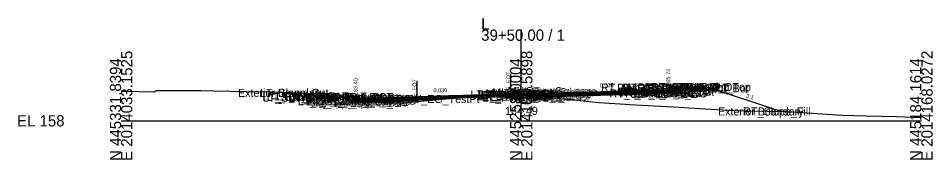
# Model space of a CAD drawing. Extents: x -26 to 4203, y -10 to 9526.
# Drawn here: x 1974.3 to 2202.8, y 9490.3 to 9525.6 of the extents above; entities that cross this region are included whole.
import ezdxf

# ---------------------------------------------------------------- set-up
doc = ezdxf.new("R2010")
doc.units = 0
for name, color, linetype in [('Default', 7, 'Continuous'), ('Exist CMT Pavement', 7, 'Continuous'), ('Exist Cross Section Cell', 7, 'Continuous'), ('Exist XS Center Line Elevation Label', 7, 'Continuous'), ('Exist XS Ground Line', 7, 'Continuous'), ('Prop CMT Conc Surface', 7, 'Continuous'), ('Prop CMT Concrete Structures', 7, 'Continuous'), ('Prop CMT Pvmt Course 1', 7, 'Continuous'), ('Prop CMT Pvmt Course 1 CG', 7, 'Continuous'), ('Prop CMT Pvmt Course 1 Wedge', 7, 'Continuous'), ('Prop CMT Pvmt Course 2', 7, 'Continuous'), ('Prop CMT Pvmt Course 2 Wedge', 7, 'Continuous'), ('Prop CMT Pvmt Course 3', 7, 'Continuous'), ('Prop CMT Pvmt Course 3 Wedge', 7, 'Continuous'), ('Prop CMT Pvmt Surface', 7, 'Continuous'), ('Prop CMT Pvmt Wedge Surface 1', 7, 'Continuous'), ('Prop CMT Pvmt Wedge Surface 2', 7, 'Continuous'), ('Prop CMT Pvmt Wedge Surface 3', 7, 'Continuous'), ('Prop CMT Slope Grass', 7, 'Continuous'), ('Prop CMT Subgrade Earthwork', 7, 'Continuous'), ('Prop XS Hydro Elevations', 7, 'Continuous'), ('Prop XS Label Text', 7, 'Continuous'), ('Prop XS SE Text', 7, 'Continuous'), ('Prop XS Side Slope Text', 7, 'Continuous'), ('Scratch_Level_0', 7, 'Continuous')]:
    doc.layers.add(name, color=color, linetype=linetype)

msp = doc.modelspace()

# ---------------------------------------------------------------- linework, layer by layer
at = {"layer": 'Exist CMT Pavement'}
for p, q in [((2073.93, 9504.85), (2080.3, 9505.44)), ((2080.3, 9505.44), (2082.24, 9505.6)), ((2082.24, 9505.6), (2084.36, 9505.77)), ((2084.36, 9505.77), (2087.3, 9506.01)), ((2087.3, 9506.01), (2088.91, 9506.12)), ((2088.91, 9506.12), (2090.43, 9506.24)), ((2090.43, 9506.24), (2091.02, 9506.29)), ((2091.02, 9506.29), (2092.45, 9506.38)), ((2092.45, 9506.38), (2093.81, 9506.46)), ((2093.81, 9506.46), (2096.86, 9506.66)), ((2096.86, 9506.66), (2097.34, 9506.68))]:
    msp.add_line(p, q, dxfattribs=at)
at = {"layer": 'Exist Cross Section Cell'}
for p, q in [((2100, 9500), (2100, 9522.77)), ((2000, 9500), (2100, 9500)), ((2100, 9500), (2200, 9500))]:
    msp.add_line(p, q, dxfattribs=at)
at = {"layer": 'Exist XS Ground Line'}
msp.add_lwpolyline([(2000, 9507.42), (2000.58, 9507.42), (2004.43, 9507.34), (2008.3, 9507.2), (2008.78, 9507.59), (2019.92, 9507.56), (2023.14, 9507.49), (2031.22, 9507.28), (2037.97, 9507.19), (2044.76, 9507.01), (2050.91, 9506.25), (2058.29, 9505.37), (2062.01, 9505), (2064.63, 9504.59), (2065.03, 9504.64), (2065.52, 9504.51), (2071.32, 9504.49), (2071.64, 9504.57), (2073.06, 9504.75), (2073.55, 9504.81), (2074, 9504.85), (2074.84, 9504.94), (2075.91, 9505.04), (2076.58, 9505.09), (2076.89, 9505.12), (2080.3, 9505.44), (2083.67, 9505.72), (2084.36, 9505.77), (2087.3, 9506.01), (2088.91, 9506.12), (2090.43, 9506.24), (2091.02, 9506.29), (2092.45, 9506.38), (2093.81, 9506.46), (2094.72, 9506.52), (2096.86, 9506.66), (2097.34, 9506.68), (2097.73, 9506.68), (2100, 9506.49), (2106.73, 9505.94), (2119.39, 9504.58), (2126.03, 9504.18), (2126.95, 9504.11), (2139.57, 9503.39), (2141.78, 9503.25), (2153.12, 9502.54), (2156.61, 9502.46), (2166.66, 9502.31), (2171.44, 9502.03), (2180.21, 9501.39), (2186.27, 9501.22), (2193.75, 9501.1), (2200, 9500.85)], dxfattribs=at)
at = {"layer": 'Prop CMT Conc Surface'}
for points in [[(2134.75, 9507.76), (2136.75, 9507.74)], [(2136.75, 9507.74), (2136.75, 9508.24), (2137.25, 9508.24)], [(2141.25, 9508.33), (2146.25, 9508.43)], [(2054.11, 9505.99), (2049.11, 9506.09)], [(2058.61, 9505.9), (2058.11, 9505.9)], [(2058.61, 9505.4), (2058.61, 9505.9)], [(2060.61, 9505.54), (2058.61, 9505.4)]]:
    msp.add_lwpolyline(points, dxfattribs=at)
at = {"layer": 'Prop CMT Concrete Structures'}
for points in [[(2108.05, 9506.96), (2108.04, 9507.12), (2107.29, 9507.37), (2103.58, 9507.45), (2099.88, 9507.11), (2099.13, 9506.86), (2099.12, 9506.69)], [(2099.12, 9506.69), (2108.05, 9506.96)], [(2134.75, 9507.76), (2136.75, 9507.74), (2136.75, 9508.24), (2137.25, 9508.24)], [(2137.25, 9508.24), (2137.25, 9507.25), (2134.75, 9507.18)], [(2134.75, 9507.18), (2134.75, 9507.76)], [(2146.25, 9508.43), (2141.25, 9508.33)], [(2141.25, 9508.33), (2141.25, 9508)], [(2141.25, 9508), (2146.25, 9508.1)], [(2146.25, 9508.1), (2146.25, 9508.43)], [(2049.11, 9505.75), (2049.11, 9506.09)], [(2049.11, 9506.09), (2054.11, 9505.99)], [(2054.11, 9505.65), (2049.11, 9505.75)], [(2054.11, 9505.99), (2054.11, 9505.65)], [(2058.61, 9505.9), (2058.11, 9505.9)], [(2058.11, 9505.9), (2058.11, 9504.88), (2060.61, 9504.95)], [(2058.61, 9505.4), (2058.61, 9505.9)], [(2060.61, 9505.54), (2058.61, 9505.4)], [(2060.61, 9504.95), (2060.61, 9505.54)]]:
    msp.add_lwpolyline(points, dxfattribs=at)
at = {"layer": 'Prop CMT Pvmt Course 1'}
for points in [[(2099.12, 9506.69), (2108.05, 9506.96)], [(2108.05, 9506.96), (2134.75, 9507.76)], [(2134.75, 9507.51), (2108.05, 9506.71)], [(2108.05, 9506.96), (2108.05, 9506.71)], [(2108.05, 9506.71), (2108.05, 9506.96)], [(2134.75, 9507.76), (2134.75, 9507.51)], [(2099.12, 9506.69), (2060.61, 9505.54)], [(2060.61, 9505.54), (2060.61, 9505.28)], [(2060.61, 9505.28), (2061.73, 9505.32)], [(2073.93, 9505.81), (2097.34, 9506.51)], [(2073.93, 9505.68), (2073.93, 9505.81)], [(2108.08, 9506.71), (2099.12, 9506.44)], [(2099.12, 9506.44), (2099.12, 9506.69)], [(2099.12, 9506.44), (2099.12, 9506.69)], [(2099.12, 9506.57), (2099.12, 9506.44), (2099.12, 9506.44)]]:
    msp.add_lwpolyline(points, dxfattribs=at)
msp.add_lwpolyline([(2108.05, 9506.71), (2108.05, 9506.83), (2108.05, 9506.83), (2108.05, 9506.71)], close=True, dxfattribs=at)
at = {"layer": 'Prop CMT Pvmt Course 1 CG'}
for points in [[(2134.75, 9507.18), (2137.75, 9507.27), (2138.07, 9506.94)], [(2134.75, 9506.84), (2134.75, 9507.18)], [(2060.61, 9504.95), (2057.61, 9504.86), (2057.27, 9504.52)], [(2060.61, 9504.62), (2060.61, 9504.95)], [(2138.07, 9506.94), (2134.75, 9506.84)], [(2057.27, 9504.52), (2060.61, 9504.62)]]:
    msp.add_lwpolyline(points, dxfattribs=at)
at = {"layer": 'Prop CMT Pvmt Course 1 Wedge'}
for points in [[(2091.97, 9506.35), (2091.02, 9506.29), (2090.43, 9506.24), (2089.12, 9506.14), (2088.91, 9506.13), (2087.3, 9506.09), (2087.04, 9506.08), (2084.36, 9506), (2083.67, 9505.98), (2083.64, 9505.98), (2083.6, 9505.98), (2080.3, 9505.88), (2080.12, 9505.87), (2079.91, 9505.86), (2076.89, 9505.77), (2076.58, 9505.76), (2075.91, 9505.74), (2074.84, 9505.71), (2074, 9505.69), (2073.55, 9505.67), (2073.06, 9505.66), (2073.02, 9505.66), (2071.64, 9505.62), (2071.32, 9505.61), (2065.52, 9505.43), (2065.52, 9505.43), (2065.03, 9505.42), (2064.63, 9505.41), (2062.01, 9505.33), (2061.73, 9505.32)], [(2073.93, 9505.81), (2074, 9505.81), (2074.84, 9505.84), (2075.91, 9505.87), (2076.58, 9505.89), (2076.89, 9505.9), (2079.91, 9505.99), (2080.12, 9506), (2080.3, 9506), (2083.6, 9506.1), (2083.64, 9506.1), (2083.67, 9506.1), (2084.36, 9506.12), (2087.04, 9506.2), (2087.3, 9506.21), (2088.91, 9506.26), (2090.43, 9506.31), (2091.02, 9506.32), (2091.97, 9506.35)], [(2073.93, 9505.68), (2073.93, 9505.81)]]:
    msp.add_lwpolyline(points, dxfattribs=at)
at = {"layer": 'Prop CMT Pvmt Course 2'}
for points in [[(2108.05, 9506.71), (2134.75, 9507.51)], [(2134.75, 9507.18), (2108.05, 9506.38)], [(2134.75, 9507.51), (2134.75, 9507.18)], [(2061.73, 9505.32), (2060.61, 9505.28)], [(2060.61, 9505.28), (2060.61, 9504.95)], [(2060.61, 9504.95), (2061.73, 9504.99)], [(2073.93, 9505.35), (2073.93, 9505.68)], [(2097.34, 9506.39), (2108.08, 9506.71)], [(2099.12, 9506.11), (2099.12, 9506.44)], [(2108.08, 9506.38), (2099.12, 9506.11)], [(2108.05, 9506.71), (2108.05, 9506.38)], [(2108.05, 9506.38), (2108.05, 9506.71)]]:
    msp.add_lwpolyline(points, dxfattribs=at)
at = {"layer": 'Prop CMT Pvmt Course 2 Wedge'}
for points in [[(2061.73, 9505.32), (2062.01, 9505.33), (2064.63, 9505.41), (2065.03, 9505.42), (2065.52, 9505.43), (2065.52, 9505.43), (2071.32, 9505.61), (2071.64, 9505.62), (2073.02, 9505.66), (2073.06, 9505.66), (2073.55, 9505.67), (2074, 9505.69), (2074.84, 9505.71), (2075.91, 9505.74), (2076.58, 9505.76), (2076.89, 9505.77), (2079.91, 9505.86), (2080.12, 9505.87), (2080.3, 9505.88), (2083.6, 9505.98), (2083.64, 9505.98), (2083.67, 9505.98), (2084.36, 9506), (2087.04, 9506.08), (2087.3, 9506.09), (2088.91, 9506.13), (2089.12, 9506.14)], [(2089.12, 9506.14), (2088.91, 9506.12), (2087.3, 9506.01), (2087.04, 9506), (2084.36, 9505.77), (2083.67, 9505.72), (2083.64, 9505.71), (2083.6, 9505.71), (2082.25, 9505.6), (2080.3, 9505.54), (2080.12, 9505.54), (2079.91, 9505.53), (2076.89, 9505.44), (2076.58, 9505.43), (2075.91, 9505.41), (2074.84, 9505.38), (2074, 9505.35), (2073.55, 9505.34), (2073.06, 9505.33), (2073.02, 9505.32), (2071.64, 9505.28), (2071.32, 9505.27), (2065.52, 9505.1), (2065.52, 9505.1), (2065.03, 9505.08), (2064.63, 9505.07), (2062.03, 9504.99), (2062.01, 9505), (2061.73, 9505.03)], [(2073.93, 9505.39), (2073.93, 9505.68)]]:
    msp.add_lwpolyline(points, dxfattribs=at)
at = {"layer": 'Prop CMT Pvmt Course 3'}
for points in [[(2108.05, 9506.38), (2134.75, 9507.18)], [(2134.75, 9507.18), (2134.75, 9506.84)], [(2060.61, 9504.62), (2073.93, 9505.02)], [(2061.73, 9504.99), (2060.61, 9504.95)], [(2060.61, 9504.95), (2060.61, 9504.62)], [(2073.93, 9505.02), (2073.93, 9505.35)], [(2097.34, 9506.05), (2108.08, 9506.38)], [(2099.12, 9505.77), (2099.12, 9506.11)], [(2108.08, 9506.04), (2099.12, 9505.77)], [(2134.75, 9506.84), (2108.05, 9506.04)], [(2108.05, 9506.38), (2108.05, 9506.04)], [(2108.05, 9506.04), (2108.05, 9506.38)]]:
    msp.add_lwpolyline(points, dxfattribs=at)
at = {"layer": 'Prop CMT Pvmt Course 3 Wedge'}
for points in [[(2062.03, 9504.99), (2064.63, 9505.07)], [(2064.63, 9505.07), (2065.03, 9505.08), (2065.52, 9505.1), (2065.52, 9505.1), (2071.32, 9505.27), (2071.64, 9505.28), (2073.02, 9505.32), (2073.06, 9505.33), (2073.55, 9505.34), (2074, 9505.35), (2074.84, 9505.38), (2075.91, 9505.41), (2076.58, 9505.43), (2076.89, 9505.44), (2079.91, 9505.53), (2080.12, 9505.54), (2080.3, 9505.54), (2082.24, 9505.6)], [(2082.24, 9505.6), (2080.3, 9505.44), (2080.12, 9505.43), (2079.91, 9505.41), (2076.89, 9505.12), (2076.58, 9505.09), (2075.91, 9505.04), (2074.84, 9504.94), (2074, 9504.85), (2073.93, 9504.85)]]:
    msp.add_lwpolyline(points, dxfattribs=at)
at = {"layer": 'Prop CMT Pvmt Surface'}
for points in [[(2099.12, 9506.69), (2108.05, 9506.96)], [(2108.05, 9506.96), (2134.75, 9507.76)], [(2099.12, 9506.69), (2060.61, 9505.54)]]:
    msp.add_lwpolyline(points, dxfattribs=at)
at = {"layer": 'Prop CMT Pvmt Wedge Surface 1'}
for points in [[(2060.61, 9505.28), (2060.61, 9505.54)], [(2061.73, 9505.32), (2060.61, 9505.28)], [(2097.34, 9506.51), (2073.93, 9505.81)], [(2073.93, 9505.81), (2073.93, 9505.68)], [(2099.12, 9506.69), (2099.12, 9506.44), (2099.12, 9506.44), (2099.12, 9506.57)]]:
    msp.add_lwpolyline(points, dxfattribs=at)
at = {"layer": 'Prop CMT Pvmt Wedge Surface 2'}
for points in [[(2097.34, 9506.39), (2060.61, 9505.28)], [(2060.61, 9505.28), (2060.61, 9505.54)], [(2099.12, 9506.69), (2099.12, 9506.44)]]:
    msp.add_lwpolyline(points, dxfattribs=at)
at = {"layer": 'Prop CMT Pvmt Wedge Surface 3'}
for points in [[(2097.34, 9506.05), (2060.61, 9504.95)], [(2060.61, 9504.95), (2060.61, 9505.54)], [(2099.12, 9506.69), (2099.12, 9506.11)]]:
    msp.add_lwpolyline(points, dxfattribs=at)
at = {"layer": 'Prop CMT Slope Grass'}
for points in [[(2137.25, 9508.24), (2146.25, 9508.42)], [(2146.25, 9508.42), (2146.75, 9508.43), (2165.04, 9502.33)], [(2058.11, 9505.9), (2048.61, 9506.09), (2046.48, 9506.8)]]:
    msp.add_lwpolyline(points, dxfattribs=at)
at = {"layer": 'Prop CMT Subgrade Earthwork'}
for q in [(2097.34, 9506.68), (2097.34, 9505.72)]:
    msp.add_line((2097.34, 9505.72), q, dxfattribs=at)
for points in [[(2134.75, 9506.84), (2138.07, 9506.94), (2139.41, 9508.28)], [(2060.61, 9504.62), (2057.27, 9504.52), (2055.84, 9505.94)], [(2073.93, 9505.02), (2060.61, 9504.62)], [(2073.93, 9504.85), (2073.93, 9505.02)], [(2097.34, 9505.72), (2108.08, 9506.04)], [(2108.05, 9506.04), (2134.75, 9506.84)]]:
    msp.add_lwpolyline(points, dxfattribs=at)
at = {"layer": 'Prop XS Label Text'}
for p, q in [((2097.34, 9511.68), (2097.34, 9506.68)), ((2073.93, 9509.85), (2073.93, 9504.85))]:
    msp.add_line(p, q, dxfattribs=at)

# ---------------------------------------------------------------- texts
at = {"layer": 'Default'}
msp.add_text('-', height=0.0001, dxfattribs=at).set_placement((2000, 9500))
at = {"layer": 'Exist Cross Section Cell'}
for s, p in [('L', (2090, 9522.77)), ('39+50.00 / 1', (2090, 9519.97)), ('EL 158', (1974, 9498.6))]:
    msp.add_text(s, height=2.8, dxfattribs=at).set_placement(p)
for s, p in [('E 2014033.1525', (2002.8, 9490)), ('E 2014100.5898', (2102.8, 9490)), ('E 2014168.0272', (2202.8, 9490)), ('N 445331.8394', (2000, 9490)), ('N 445258.0004', (2100, 9490)), ('N 445184.1614', (2200, 9490))]:
    msp.add_text(s, height=2.8, rotation=90, dxfattribs=at).set_placement(p)
at = {"layer": 'Exist XS Center Line Elevation Label'}
msp.add_text('164.49', height=2, dxfattribs=at).set_placement((2095.97, 9501.49))
at = {"layer": 'Prop XS Hydro Elevations'}
for s, p in [('165.74', (2137.25, 9508.74)), ('163.40', (2059.11, 9506.4))]:
    msp.add_text(s, height=1, rotation=90, dxfattribs=at).set_placement(p)
at = {"layer": 'Prop XS Label Text'}
for p in [(2097.24, 9507.71), (2073.83, 9505.87)]:
    msp.add_text('E. EOT', height=1, rotation=90, dxfattribs=at).set_placement(p)
at = {"layer": 'Prop XS SE Text'}
for rotation, p in [(1.7181, (2119.64, 9508.31)), (1.718, (2078.08, 9507.06))]:
    msp.add_text('0.030', height=1, rotation=rotation, dxfattribs=at).set_placement(p)
at = {"layer": 'Prop XS Side Slope Text'}
for p in [(2047.31, 9507.15), (2156.09, 9505.87)]:
    msp.add_text('3:1', height=1, rotation=341.5651, dxfattribs=at).set_placement(p)
at = {"layer": 'Scratch_Level_0'}
for s, p in [('RT_Sub_Trench_Out_DLT', (2119.93, 9507.28)), ('RT_CG_Top_Face', (2123.96, 9507.24)), ('RT_CG_Top_BOC', (2125.49, 9507.24)), ('RT_SDWK_In_Top', (2129.06, 9507.33)), ('RT_SDWK_Out_Top', (2132.44, 9507.43)), ('RT_Shld_O', (2138.79, 9507.42)), ('CSLP_Pnt', (2139.62, 9507.43)), ('Exterior Boundary', (2029.22, 9505.97)), ('LT_Slope_Cut', (2034.71, 9505.97)), ('LT_SDWK_Out_Top', (2035.34, 9505.09)), ('LT_Sub_Trench_Out_DLT', (2036.41, 9504.94)), ('LT_CSLP_Pnt', (2038.78, 9505.09)), ('LT_SDWK_In_Top', (2041.97, 9504.99)), ('LT_PV_IEEOP_EG', (2087.31, 9505.57)), ('LT_PV2_IEEOP', (2089.07, 9505.44)), ('LT_PV3_IEEOP', (2089.07, 9505.11)), ('LT_PV1_IEEOP', (2089.64, 9505.57)), ('LT_PV2_PGL1', (2090, 9505.44)), ('LT_PV3_PGL1', (2090, 9505.11)), ('LT_PV2_PGL', (2090.33, 9505.44)), ('LT_PV3_PGL', (2090.33, 9505.11)), ('LT_PV1_PGL', (2090.9, 9505.69)), ('MI_Face In', (2091.02, 9505.86)), ('MI_Top In', (2092.73, 9506.11)), ('MI_Top In', (2092.73, 9506.11)), ('MI_Crown', (2096.67, 9506.45)), ('RT_Sub_OEEOP', (2097.24, 9505.04)), ('RT_PV2_OEEOP', (2097.34, 9505.71)), ('RT_PV3_OEEOP', (2097.34, 9505.38)), ('RT_PV1_OEEOP', (2097.91, 9505.84)), ('RT_PV2_IEEOP', (2097.98, 9505.71)), ('MI_Face Out', (2098.34, 9506.13)), ('MI_Top Out', (2098.55, 9506.38)), ('RT_PV1_IEEOP', (2098.55, 9505.84)), ('RT_PV2_PGL1', (2098.91, 9505.71)), ('RT_PV3_PGL1', (2098.91, 9505.38)), ('RT_PV2_PGL', (2099.24, 9505.71)), ('RT_PV4_PGL', (2099.24, 9505.04)), ('MI_Bot Out', (2099.34, 9505.96)), ('RT_PV1_PGL', (2099.81, 9505.96)), ('RT_Sub_OEOT_CG', (2122.07, 9505.84)), ('RT_CG1_Shelf_Out', (2124.25, 9506.27)), ('RT_CG_Bot_IE', (2124.62, 9506.18)), ('RT_Sub_OEOT', (2124.78, 9505.84)), ('RT_PV2_OEOT', (2124.88, 9506.51)), ('RT_PV3_OEOT', (2124.88, 9506.18)), ('RT_CG_Top_Gut', (2124.94, 9506.74)), ('RT_PV1_OEOT', (2125.44, 9506.76)), ('RT_CG_Bot_BOC', (2125.52, 9506.25)), ('RT_Sub_OEOP', (2128.14, 9505.94)), ('RT_SDWK_In_Bot', (2129.09, 9507)), ('RT_SDWK_Out_Bot', (2132.47, 9507.1)), ('LT_SDWK_Out_Bot', (2035.38, 9504.75)), ('LT_SDWK_In_Bot', (2042, 9504.65)), ('LT_CG1_Shelf_Out', (2044.16, 9503.86)), ('LT_CG_Top_Face', (2045.87, 9504.9)), ('LT_CG_Top_BOC', (2046.39, 9504.9)), ('LT_CG_Bot_BOC', (2046.42, 9503.88)), ('LT_PV_Sub_Tie_Out', (2046.69, 9504.02)), ('LT_CG_Top_Gut', (2046.85, 9504.4)), ('LT_Sub_OEOP', (2047.38, 9503.52)), ('LT_Sub_OEOT_CG', (2047.98, 9503.62)), ('LT_PV_OEEOP_EG', (2049.28, 9504.03)), ('LT_CG_Bot_IE', (2050.52, 9503.95)), ('LT_Sub_OEOT', (2050.69, 9503.62)), ('LT_PV2_OEOT', (2050.78, 9504.28)), ('LT_PV3_OEOT', (2050.78, 9503.95)), ('LT_Sub_OEEOP', (2050.94, 9503.65)), ('LT_PV2_OEEOP', (2051.04, 9504.32)), ('LT_PV3_OEEOP', (2051.04, 9503.99)), ('LT_PV1_OEOT', (2051.35, 9504.54)), ('LT_PV1_OEEOP', (2051.61, 9504.44)), ('LT_PV_EG_TestPt', (2066.83, 9504.45)), ('LT_PV4_PGL', (2090.33, 9504.77)), ('Exterior Boundary', (2149.18, 9501.33)), ('RT_Slope_Fill', (2155.51, 9501.33))]:
    msp.add_text(s, height=2, dxfattribs=at).set_placement(p)

doc.saveas('drawing.dxf')
